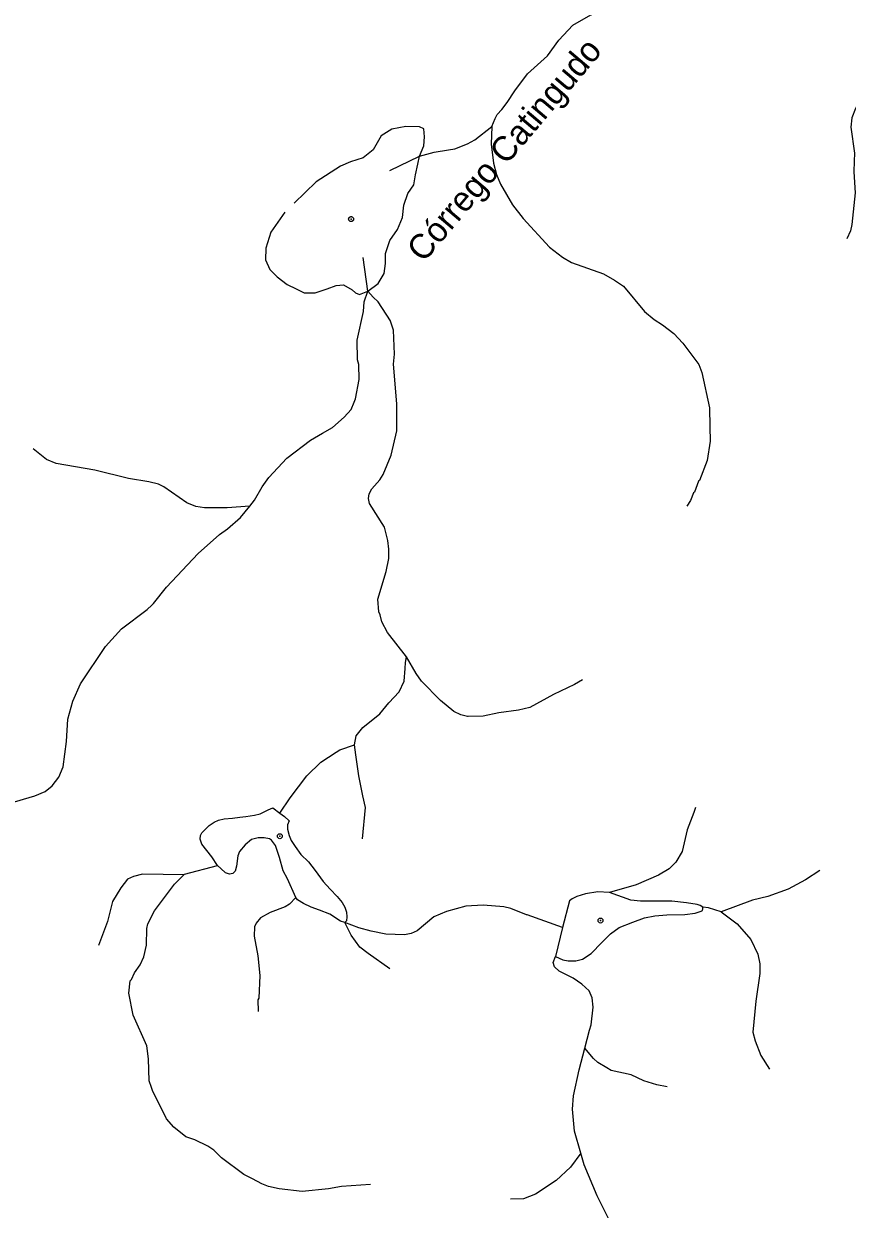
# Model space of a CAD drawing. Extents: x 396 to 422.2, y 7649.8 to 7677.6.
# Drawn here: x 406.434 to 409.113, y 7662.102 to 7665.958 of the extents above; entities that cross this region are included whole.
import ezdxf
from ezdxf.enums import TextEntityAlignment as Align

# ---------------------------------------------------------------- set-up
doc = ezdxf.new("R2010")
doc.units = 0
doc.header["$LTSCALE"] = 0.032
doc.header["$PDMODE"] = 32
doc.header["$PDSIZE"] = 0.016
doc.linetypes.add('SHORT_DASHED', pattern=[2.7, 1.5, -1.2])
for name, color, linetype, lineweight in [('2', 7, 'Continuous', 25), ('21', 7, 'SHORT_DASHED', 13), ('7', 7, 'Continuous', 25)]:
    doc.layers.add(name, color=color, linetype=linetype, lineweight=lineweight)
doc.layers.add('61', color=7, linetype='Continuous')

msp = doc.modelspace()

# ---------------------------------------------------------------- linework, layer by layer
at = {"layer": '2'}
for points in [[(407.019, 7663.3316), (407.0376, 7663.3495), (407.0537, 7663.3609), (407.0675, 7663.3675), (407.0867, 7663.3711), (407.113, 7663.3735), (407.1375, 7663.3771), (407.1567, 7663.3789), (407.1854, 7663.383), (407.2034, 7663.3878), (407.2291, 7663.4004), (407.2442, 7663.4072), (407.2678, 7663.3901)], [(407.2678, 7663.3901), (407.2823, 7663.3795), (407.2974, 7663.3656), (407.2926, 7663.3519), (407.2926, 7663.3376), (407.2974, 7663.3172), (407.3045, 7663.3016), (407.3171, 7663.2813), (407.3357, 7663.2561), (407.3602, 7663.2316), (407.3818, 7663.2035), (407.4087, 7663.1676), (407.4314, 7663.1424), (407.4542, 7663.1191), (407.4703, 7663.0999), (407.4793, 7663.0838), (407.4841, 7663.0676), (407.4853, 7663.0532), (407.4847, 7663.0401), (407.4792, 7663.0342)], [(407.0644, 7663.2196), (407.0466, 7663.2478), (407.0136, 7663.2897), (407.0083, 7663.3052), (407.0094, 7663.3172), (407.0142, 7663.3256), (407.019, 7663.3316)], [(407.319, 7663.1153), (407.2926, 7663.1759), (407.2782, 7663.2029), (407.2662, 7663.2454), (407.2531, 7663.2843), (407.2399, 7663.3022), (407.2333, 7663.3064), (407.2165, 7663.31), (407.1974, 7663.31), (407.1758, 7663.3046), (407.1543, 7663.2873), (407.1363, 7663.2651), (407.131, 7663.2514), (407.1268, 7663.2178), (407.122, 7663.2011), (407.1148, 7663.1939), (407.104, 7663.1921), (407.0909, 7663.1963), (407.0759, 7663.2095), (407.0644, 7663.2196)], [(408.34, 7663.132), (408.3011, 7663.1346), (408.2616, 7663.1275), (408.2329, 7663.1191), (408.2185, 7663.1119), (408.209, 7663.1047), (408.1871, 7663.0178), (408.1635, 7662.9239)], [(408.6429, 7663.084), (408.6342, 7663.0893), (408.6244, 7663.0927), (408.5896, 7663.0987), (408.5418, 7663.1035), (408.4831, 7663.1035), (408.44, 7663.1035), (408.4089, 7663.1071), (408.34, 7663.132)], [(407.4792, 7663.0342), (407.4649, 7663.0389), (407.4296, 7663.0616), (407.3967, 7663.0748), (407.3698, 7663.0844), (407.3446, 7663.0963), (407.3249, 7663.1083), (407.319, 7663.1153)], [(408.1635, 7662.9239), (408.1874, 7662.9132), (408.2054, 7662.9096), (408.2305, 7662.9096), (408.252, 7662.9156), (408.2796, 7662.9335), (408.3143, 7662.9694), (408.343, 7662.997), (408.3706, 7663.0185), (408.4149, 7663.0353), (408.4532, 7663.0496), (408.4867, 7663.0556), (408.5262, 7663.0592), (408.5848, 7663.0604), (408.6184, 7663.0652), (408.6375, 7663.0712), (408.6418, 7663.0736), (408.6436, 7663.0788), (408.6429, 7663.084)]]:
    msp.add_lwpolyline(points, dxfattribs=at)
for p in [(407.2673, 7663.315), (408.3104, 7663.0406)]:
    msp.add_point(p, dxfattribs=at)
at = {"layer": '21'}
for points in [[(407.7221, 7665.5266), (407.736, 7665.5607), (407.7376, 7665.5899), (407.736, 7665.6158), (407.7214, 7665.6223), (407.6776, 7665.6239), (407.6322, 7665.6142), (407.5965, 7665.5931), (407.5706, 7665.5477), (407.5381, 7665.5218), (407.4976, 7665.5088), (407.4652, 7665.4942), (407.3857, 7665.4439), (407.2835, 7665.345), (407.2381, 7665.2801), (407.2219, 7665.2282), (407.2203, 7665.1893), (407.2349, 7665.1585), (407.2592, 7665.1341), (407.2916, 7665.1098), (407.3208, 7665.0952), (407.3468, 7665.0822), (407.3824, 7665.0822), (407.4214, 7665.0952), (407.4506, 7665.1066), (407.4749, 7665.1082), (407.5025, 7665.092), (407.5138, 7665.0822), (407.5268, 7665.0774), (407.5538, 7665.0879)], [(407.5538, 7665.0879), (407.5868, 7665.1131), (407.6063, 7665.1455), (407.6111, 7665.1779), (407.6111, 7665.2104), (407.6257, 7665.2525), (407.65, 7665.2882), (407.6663, 7665.3271), (407.6711, 7665.3677), (407.6841, 7665.405), (407.7036, 7665.4342), (407.7084, 7665.4666), (407.7165, 7665.5007), (407.7221, 7665.5266)]]:
    msp.add_lwpolyline(points, dxfattribs=at)
msp.add_point((407.4992, 7665.3223), dxfattribs=at)
at = {"layer": '7'}
for p, q in [((407.6252, 7665.4808), (407.7221, 7665.5266)), ((407.5538, 7665.0879), (407.538, 7665.1973))]:
    msp.add_line(p, q, dxfattribs=at)
for points in [[(407.9564, 7665.6232), (407.9682, 7665.6489), (407.9742, 7665.6628), (407.9894, 7665.6789), (408.007, 7665.7019), (408.0317, 7665.7398), (408.0732, 7665.795), (408.1383, 7665.8536), (408.1747, 7665.9045), (408.2204, 7665.9526), (408.2789, 7665.9863), (408.3101, 7666.0077), (408.3478, 7666.0409), (408.3762, 7666.0725), (408.4164, 7666.1075), (408.5038, 7666.1602), (408.5275, 7666.1793), (408.5819, 7666.2234), (408.6128, 7666.2357), (408.635, 7666.2374), (408.6686, 7666.2342), (408.6801, 7666.2384), (408.7089, 7666.2603), (408.7176, 7666.2705)], [(409.27, 7665.8786), (409.2426, 7665.8256), (409.1917, 7665.7684), (409.1706, 7665.7383), (409.1631, 7665.7248), (409.1391, 7665.6815), (409.1276, 7665.6515), (409.1249, 7665.6209), (409.1359, 7665.537), (409.1352, 7665.5103), (409.1343, 7665.476), (409.1383, 7665.4073), (409.1279, 7665.3051), (409.1232, 7665.2844), (409.1113, 7665.2581)], [(407.7221, 7665.5266), (407.7694, 7665.5396), (407.8163, 7665.5475), (407.8368, 7665.551), (407.878, 7665.567), (407.9012, 7665.5805), (407.9564, 7665.6232)], [(407.9564, 7665.6232), (407.9542, 7665.5663), (407.9621, 7665.5041), (407.9722, 7665.4669), (407.9855, 7665.436), (408.0236, 7665.3684), (408.0592, 7665.324), (408.1439, 7665.2308), (408.1864, 7665.1985), (408.2159, 7665.1813), (408.3204, 7665.1439), (408.3563, 7665.1239), (408.385, 7665.1039), (408.4534, 7665.0212), (408.4844, 7664.9956), (408.5121, 7664.9785), (408.5487, 7664.9497), (408.5782, 7664.9185), (408.6303, 7664.8489), (408.64, 7664.8231), (408.6646, 7664.7089), (408.666, 7664.647), (408.667, 7664.6001), (408.6573, 7664.5376), (408.6319, 7664.472), (408.6288, 7664.4698), (408.6162, 7664.4341), (408.6129, 7664.4324), (408.6032, 7664.4072), (408.5905, 7664.3888)], [(407.1698, 7664.389), (407.1853, 7664.4081), (407.2097, 7664.451), (407.2321, 7664.4817), (407.2905, 7664.545), (407.3673, 7664.6036), (407.4065, 7664.6261), (407.4392, 7664.6449), (407.4769, 7664.678), (407.4998, 7664.7031), (407.5097, 7664.7271), (407.5138, 7664.7372), (407.5258, 7664.8007), (407.5242, 7664.8489), (407.5195, 7664.8649), (407.5187, 7664.9289), (407.5392, 7665.022), (407.5418, 7665.0531), (407.5538, 7665.0879)], [(407.6791, 7663.8989), (407.6174, 7663.9776), (407.5987, 7664.0124), (407.5938, 7664.0356), (407.5889, 7664.0448), (407.5857, 7664.0861), (407.6136, 7664.1762), (407.6215, 7664.2186), (407.6223, 7664.2483), (407.619, 7664.277), (407.6078, 7664.3197), (407.5595, 7664.3972), (407.5554, 7664.4138), (407.5583, 7664.4288), (407.5664, 7664.4453), (407.5922, 7664.4744), (407.6033, 7664.492), (407.6299, 7664.5547), (407.6478, 7664.6333), (407.6478, 7664.721), (407.6367, 7664.8502), (407.6398, 7664.8824), (407.6366, 7664.9605), (407.6278, 7664.9902), (407.6271, 7664.9913), (407.5877, 7665.0532), (407.5706, 7665.0681), (407.5538, 7665.0879)], [(407.1698, 7664.389), (407.0964, 7664.3832), (407.0223, 7664.3832), (406.9946, 7664.3878), (406.9654, 7664.3998), (406.8899, 7664.4517), (406.8729, 7664.4596), (406.8415, 7664.4676), (406.7755, 7664.4782), (406.6657, 7664.506), (406.5402, 7664.5277), (406.5091, 7664.5407), (406.4652, 7664.5754)], [(406.3865, 7663.4211), (406.4709, 7663.4469), (406.5045, 7663.4606), (406.5271, 7663.4786), (406.5488, 7663.5068), (406.5632, 7663.5411), (406.5736, 7663.6236), (406.5776, 7663.6961), (406.5938, 7663.7538), (406.6189, 7663.8103), (406.7001, 7663.9324), (406.753, 7663.99), (406.8357, 7664.052), (406.8516, 7664.0667), (406.857, 7664.0716), (406.8984, 7664.1251), (407.0022, 7664.2343), (407.071, 7664.296), (407.0973, 7664.3143), (407.1399, 7664.3521), (407.1698, 7664.389)], [(407.5102, 7663.6121), (407.5162, 7663.6415), (407.5377, 7663.6686), (407.5921, 7663.7134), (407.6218, 7663.7494), (407.6558, 7663.7851), (407.6718, 7663.8192), (407.675, 7663.8607), (407.6763, 7663.8799), (407.6791, 7663.8989)], [(408.2516, 7663.8234), (408.2256, 7663.808), (408.1569, 7663.7764), (408.0801, 7663.7338), (408.0438, 7663.7245), (407.9793, 7663.7164), (407.9289, 7663.7054), (407.8801, 7663.7045), (407.8779, 7663.7045), (407.8559, 7663.7099), (407.8331, 7663.7203), (407.7896, 7663.7564), (407.7281, 7663.8196), (407.7104, 7663.8439), (407.6791, 7663.8989)], [(407.2678, 7663.3901), (407.3005, 7663.4401), (407.3554, 7663.5112), (407.4004, 7663.5559), (407.4503, 7663.588), (407.4622, 7663.5957), (407.5102, 7663.6121)], [(407.5367, 7663.3064), (407.5457, 7663.4083), (407.5378, 7663.446), (407.5241, 7663.5115), (407.5146, 7663.58), (407.5102, 7663.6121)], [(408.6193, 7663.4079), (408.6133, 7663.3922), (408.5918, 7663.3361), (408.5754, 7663.2652), (408.555, 7663.2307), (408.5332, 7663.2087), (408.4992, 7663.1884), (408.426, 7663.1564), (408.34, 7663.132)], [(406.9556, 7663.1894), (406.9573, 7663.1911), (407.0644, 7663.2196)], [(406.9556, 7663.1894), (406.8213, 7663.1918), (406.7913, 7663.1845), (406.7722, 7663.1757), (406.7499, 7663.1473), (406.7237, 7663.1028), (406.7065, 7663.0379), (406.6773, 7662.9597)], [(407.5626, 7662.1822), (407.4685, 7662.1757), (407.4258, 7662.1677), (407.34, 7662.1597), (407.2653, 7662.1682), (407.2311, 7662.1754), (407.2085, 7662.1842), (407.1784, 7662.2002), (407.1504, 7662.2152), (407.0779, 7662.2688), (407.0532, 7662.2935), (407.0333, 7662.3073), (406.991, 7662.3279), (406.9621, 7662.3377), (406.9227, 7662.3682), (406.8988, 7662.3961), (406.8537, 7662.4879), (406.8502, 7662.4975), (406.8423, 7662.519), (406.8399, 7662.5911), (406.8344, 7662.6331), (406.79, 7662.7332), (406.7769, 7662.8042), (406.7802, 7662.8442), (406.7838, 7662.8481), (406.7851, 7662.8495), (406.7946, 7662.8712), (406.8128, 7662.8967), (406.825, 7662.9228), (406.8343, 7662.9604), (406.8344, 7663.015), (406.8378, 7663.0297), (406.8601, 7663.0724), (406.9251, 7663.1588), (406.9556, 7663.1894)], [(409.0236, 7663.2038), (408.9771, 7663.1729), (408.9201, 7663.1432), (408.8549, 7663.119), (408.8045, 7663.1067), (408.7029, 7663.0689)], [(407.319, 7663.1153), (407.2985, 7663.0938), (407.2848, 7663.0852), (407.236, 7663.0664), (407.2046, 7663.0497), (407.1904, 7663.0326), (407.1852, 7663.0207), (407.1836, 7662.9895), (407.1956, 7662.9257), (407.202, 7662.8619), (407.1996, 7662.7885), (407.1964, 7662.7826), (407.1965, 7662.7444)], [(408.1871, 7663.0178), (408.0714, 7663.0591), (408.0697, 7663.0598), (408.0191, 7663.0801), (407.9956, 7663.085), (407.9285, 7663.0913), (407.8727, 7663.088), (407.809, 7663.0707), (407.7683, 7663.0532), (407.7145, 7663.0073), (407.6945, 7662.9989), (407.673, 7662.9939), (407.6123, 7662.9968), (407.5641, 7663.0061), (407.5247, 7663.0171), (407.4792, 7663.0342)], [(408.7029, 7663.0689), (408.6614, 7663.0821), (408.6429, 7663.084)], [(408.7029, 7663.0689), (408.7542, 7663.0304), (408.7996, 7662.9793), (408.8218, 7662.9314), (408.8281, 7662.8998), (408.8281, 7662.868), (408.8154, 7662.779), (408.8059, 7662.6778), (408.8129, 7662.6495), (408.832, 7662.6019), (408.8601, 7662.5578)], [(407.6252, 7662.8837), (407.5546, 7662.9339), (407.5277, 7662.9538), (407.4995, 7662.9927), (407.4792, 7663.0342)], [(408.2592, 7662.6255), (408.2747, 7662.6844), (408.2794, 7662.702), (408.2866, 7662.7595), (408.2827, 7662.7895), (408.2729, 7662.812), (408.2494, 7662.8334), (408.2209, 7662.8529), (408.1756, 7662.8763), (408.1604, 7662.8905), (408.1567, 7662.9042), (408.1635, 7662.9239)], [(408.2462, 7662.2836), (408.2253, 7662.3556), (408.2188, 7662.4277), (408.222, 7662.4705), (408.2408, 7662.5556), (408.2592, 7662.6255)], [(408.5275, 7662.5004), (408.494, 7662.5068), (408.4515, 7662.5198), (408.4102, 7662.5385), (408.3445, 7662.5531), (408.3309, 7662.5614), (408.302, 7662.579), (408.2872, 7662.5923), (408.2592, 7662.6255)], [(408.2462, 7662.2836), (408.2128, 7662.2384), (408.1657, 7662.195), (408.0987, 7662.1503), (408.0599, 7662.1356), (408.0171, 7662.1343)], [(408.4588, 7661.7709), (408.4001, 7661.9054), (408.3746, 7661.9852), (408.3495, 7662.0452), (408.2993, 7662.1454), (408.257, 7662.2464), (408.2462, 7662.2836)]]:
    msp.add_lwpolyline(points, dxfattribs=at)

# ---------------------------------------------------------------- texts
at = {"layer": '61'}
msp.add_text('Córrego Catingudo', height=0.08, rotation=49.737, dxfattribs=at).set_placement((408.0269, 7665.5229), align=Align.CENTER)

doc.saveas('drawing.dxf')
